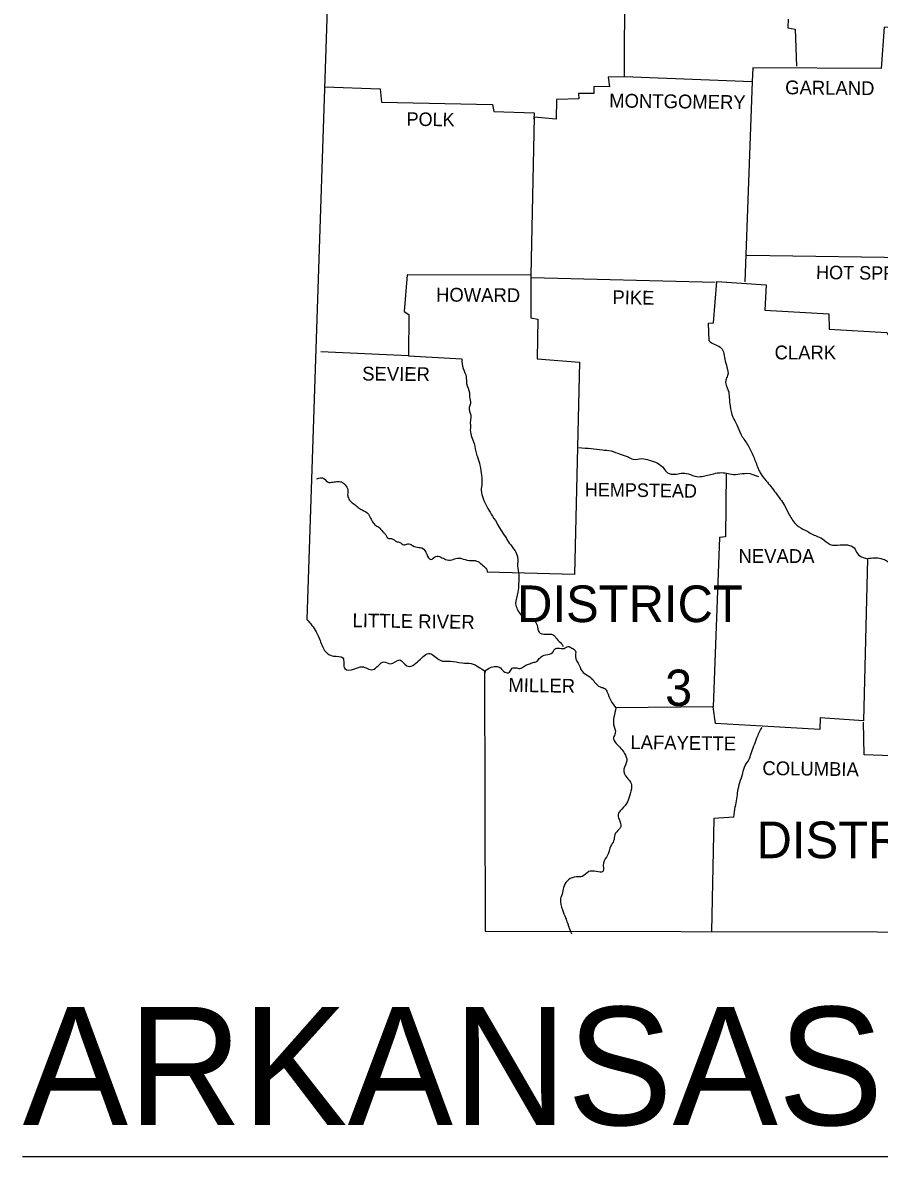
# Model space of a CAD drawing. Extents: x -42408 to 34530, y -43140 to 20491.
# Drawn here: x 1234 to 2569, y -23266 to -21499 of the extents above; entities that cross this region are included whole.
import ezdxf

# ---------------------------------------------------------------- set-up
doc = ezdxf.new("R2010")
doc.units = 0
for name, color, linetype in [('1', 7, 'Continuous'), ('2', 7, 'Continuous'), ('3', 7, 'Continuous')]:
    doc.layers.add(name, color=color, linetype=linetype)

msp = doc.modelspace()

# ---------------------------------------------------------------- linework, layer by layer
at = {"layer": '1'}
for points in [[(1618, -20239.1), (1721.6, -21071.2), (1676.6, -22429.5)], [(2172.2, -21291), (2171.2, -21583.9), (2146.2, -21584.4), (2148.2, -21599.4), (2124.1, -21598.9), (2123.6, -21609.9), (2100.1, -21609.9), (2100.6, -21617.9), (2065.6, -21618.9), (2065.1, -21649.5), (2031, -21646.5), (2025.5, -21892.8), (1832.8, -21892.3), (1828.3, -21949.4), (1835.3, -21954.4), (1834.8, -22018.5), (1698.1, -22012.5)], [(2426.6, -21493.8), (2426.1, -21507.3), (2437.6, -21509.3), (2439.6, -21567.4)], [(2740, -21511.3), (2576.3, -21506.3), (2571.7, -21570.9), (2371.5, -21569.9), (2370.5, -21591.4)], [(2370.5, -21591.4), (2171.2, -21583.9)], [(1704.1, -21599.4), (1790.7, -21602.4), (1792.7, -21623.4), (1965.9, -21626.9), (1967.9, -21638), (2031, -21640), (2030.5, -21649.5)], [(2370.5, -21591.4), (2359, -21903.3)], [(2362.5, -21861.8), (2648.8, -21865.8), (2654.4, -21818.2), (2676.9, -21818.2), (2677.4, -21778.1), (2785.5, -21779.7), (2784.5, -21803.7), (2812.6, -21805.7), (2812.6, -21849.7), (2830.6, -21851.2)], [(2025.5, -21892.8), (2025.5, -21959.4), (2036.5, -21961.4), (2035.5, -22023.5), (2101.6, -22028.5), (2093.6, -22359.4), (1957.4, -22355.9)], [(2026.5, -21896.3), (2312.9, -21903.8)], [(2303.4, -21995.4), (2302.4, -21967.9), (2310.4, -21967.4), (2315.4, -21902.8), (2392.5, -21907.8), (2390.5, -21947.4), (2490.1, -21952.9), (2490.6, -21976.9), (2580.8, -21982.4), (2596.3, -22009.5), (2586.8, -22021.5), (2591.3, -22040), (2917.7, -22052)], [(1834.8, -22018.5), (1917.9, -22023.5)], [(2329.9, -22201.2), (2328.9, -22300.8), (2319.9, -22301.8), (2309.9, -22565.7)], [(2550.7, -22334.9), (2544.2, -22587.2), (2476.6, -22582.7), (2476.1, -22601.2), (2386, -22595.7)], [(1953.4, -22510.1), (1954.4, -22915.2), (3789.4, -22918.2)], [(2386, -22595.7), (2313.4, -22591.7), (2309.9, -22565.7), (2158.2, -22567.2)], [(2759, -22648.3), (2545.2, -22640.3), (2544.2, -22589.7)], [(2341.9, -22737.4), (2310.9, -22739.4), (2307.4, -22915.7)]]:
    msp.add_lwpolyline(points, dxfattribs=at)
for points in [[(2303.4, -21995.4), (2311.4, -22000.4), (2320.9, -22005), (2325.9, -22012.5), (2327.9, -22024), (2331.4, -22036.5), (2332.4, -22049.5), (2329.4, -22056.5), (2333.4, -22072.5), (2334.9, -22083.6), (2336.4, -22096.6), (2340.4, -22114.1), (2346.9, -22126.1), (2353, -22140.6), (2363, -22156.2), (2371.5, -22173.2), (2375.5, -22182.2), (2383, -22200.7), (2392.5, -22213.2), (2407.5, -22232.3), (2421, -22251.8), (2428.6, -22266.3), (2440.1, -22282.3), (2453.1, -22290.3), (2469.6, -22298.8), (2480.1, -22303.9), (2492.1, -22312.4), (2507.7, -22313.4), (2519.2, -22313.4), (2529.7, -22317.9), (2534.7, -22326.9), (2543.7, -22332.9), (2550.7, -22334.9)], [(1917.9, -22023.5), (1920.4, -22038.5), (1924.9, -22051.5), (1925.4, -22061.5), (1929.9, -22076.5), (1929.9, -22082.1), (1931.4, -22093.1), (1929.4, -22099.1), (1931.9, -22111.1), (1931.4, -22120.1), (1931.4, -22127.6), (1931.9, -22140.1), (1935.9, -22151.1), (1939.9, -22167.7), (1942.4, -22176.2), (1946.4, -22189.2), (1948.9, -22205.2), (1949.4, -22217.2), (1948.4, -22228.2), (1951.4, -22240.8), (1956.9, -22253.3), (1963.9, -22265.3), (1972.4, -22278.8), (1978.5, -22289.3), (1986, -22300.8), (1992, -22310.4), (2001, -22322.4), (2005, -22332.4), (2005, -22346.4), (2007, -22359.4), (2006.5, -22373.9), (2005.5, -22387), (2002, -22405), (2004.5, -22413.5), (2014, -22426), (2020, -22429.5), (2030.5, -22431.5), (2035.5, -22438.5), (2038.5, -22449), (2049, -22452.5), (2060.6, -22453.5), (2066.1, -22459.6), (2073.6, -22467.6), (2076.1, -22471.6)], [(2100.6, -22161.7), (2119.6, -22163.2), (2137.2, -22165.2), (2150.7, -22166.7), (2164.7, -22171.7), (2177.2, -22176.2), (2185.2, -22179.7), (2198.7, -22178.7), (2210.3, -22181.2), (2223.3, -22185.7), (2232.8, -22194.2), (2238.8, -22200.7), (2250.3, -22203.2), (2259.8, -22201.7), (2271.3, -22202.7), (2284.4, -22206.7), (2294.9, -22206.2), (2303.4, -22204.2), (2313.4, -22201.7), (2325.9, -22200.7), (2335.4, -22202.7), (2347.9, -22203.2), (2362.5, -22201.7), (2380.5, -22206.7)], [(1692.1, -22210.2), (1703.1, -22209.7), (1710.6, -22216.2), (1715.1, -22215.7), (1723.1, -22214.7), (1730.6, -22215.2), (1736.1, -22219.7), (1740.6, -22227.7), (1740.1, -22235.3), (1740.6, -22238.3), (1744.1, -22244.8), (1750.1, -22249.8), (1756.7, -22254.8), (1762.7, -22258.8), (1772.7, -22265.3), (1773.7, -22267.3), (1777.7, -22275.3), (1782.7, -22281.8), (1788.7, -22285.8), (1795.2, -22292.8), (1798.2, -22295.8), (1803.2, -22302.8), (1808.7, -22303.3), (1816.2, -22307.9), (1821.7, -22309.4), (1827.8, -22313.4), (1833.8, -22311.4), (1841.3, -22314.4), (1851.3, -22317.4), (1856.8, -22318.4), (1863.3, -22327.9), (1869.8, -22335.9), (1877.8, -22331.4), (1892.8, -22335.9), (1902.4, -22336.4), (1910.9, -22333.9), (1917.4, -22334.4), (1929.4, -22337.4), (1936.9, -22337.4), (1944.9, -22340.4), (1952.4, -22346.4), (1957.4, -22352.9), (1957.4, -22355.9)], [(2667.4, -22308.9), (2654.4, -22317.4), (2644.3, -22321.4), (2636.8, -22323.9), (2629.8, -22325.9), (2620.8, -22331.9), (2613.8, -22336.9), (2604.3, -22341.4), (2595.3, -22344.4), (2584.3, -22340.9), (2578.3, -22337.4), (2571.7, -22334.9), (2550.7, -22334.9)], [(1676.6, -22429.5), (1691.1, -22448.5), (1697.1, -22462.1), (1705.6, -22479.6), (1718.1, -22486.6), (1732.6, -22489.1), (1735.6, -22506.1), (1750.6, -22506.6), (1762.7, -22503.1), (1779.2, -22507.6), (1796.7, -22495.6), (1806.7, -22498.6), (1821.2, -22492.6), (1832.3, -22501.6), (1851.3, -22493.6), (1868.3, -22482.6), (1884.3, -22493.1), (1899.8, -22494.6), (1918.4, -22497.1), (1932.9, -22498.1), (1945.9, -22504.6), (1955.4, -22511.1), (1953.4, -22510.1)], [(1953.4, -22510.1), (1970.9, -22502.6), (1978.5, -22505.1), (1985, -22511.6), (1992.5, -22511.6), (1996.5, -22505.6), (2004, -22505.1), (2010, -22505.6), (2016.5, -22501.6), (2022, -22499.1), (2029.5, -22496.6), (2035, -22494.6), (2040, -22489.1), (2049, -22484.6), (2059.6, -22481.1), (2062.6, -22476.1), (2067.6, -22474.1), (2077.6, -22474.6), (2084.1, -22471.6), (2089.6, -22474.1), (2094.6, -22477.6), (2095.6, -22490.6), (2099.6, -22497.6), (2105.6, -22510.1), (2114.1, -22516.6), (2122.1, -22523.1), (2125.1, -22527.1), (2133.7, -22534.7), (2141.2, -22537.2), (2144.7, -22542.7), (2150.2, -22555.7), (2158.2, -22567.2)], [(2158.2, -22567.2), (2155.2, -22581.7), (2154.7, -22593.2), (2157.2, -22606.8), (2154.7, -22613.3), (2158.7, -22622.8), (2166.2, -22630.3), (2171.7, -22638.3), (2175.2, -22649.8), (2170.7, -22662.8), (2175.7, -22676.3), (2180.2, -22681.4), (2182.7, -22689.4), (2179.2, -22704.9), (2174.7, -22716.4), (2164.7, -22727.9), (2161.7, -22733.4), (2163.2, -22740.9), (2165.7, -22752.9), (2163.2, -22756.5), (2156.7, -22765), (2154.7, -22774.5), (2150.2, -22782.5), (2145.2, -22797), (2138.7, -22809), (2137.7, -22822.5), (2127.7, -22822.5), (2116.1, -22822.5), (2105.6, -22830.1), (2096.1, -22830.6), (2084.6, -22835.1), (2077.6, -22844.6), (2075.1, -22855.1), (2072.1, -22865.1), (2075.1, -22882.1), (2079.6, -22894.1), (2083.1, -22903.7), (2089.1, -22919.2)], [(2341.9, -22737.4), (2344.4, -22721.4), (2346.9, -22708.9), (2348.4, -22696.9), (2351.5, -22683.4), (2356, -22668.8), (2360, -22656.8), (2365.5, -22648.3), (2369, -22638.3), (2373.5, -22626.3), (2378, -22613.8), (2386, -22597.7)]]:
    msp.add_spline(points, degree=3, dxfattribs=at)
at = {"layer": '2'}
msp.add_line((1233.5, -23266.2), (4582.8, -23266.2), dxfattribs=at)

# ---------------------------------------------------------------- texts
for s, height, rotation, p in [('GARLAND', 21.53, 359.3658, (2422, -21610.9)), ('MONTGOMERY', 21.53, 359.2944, (2147.7, -21631.5)), ('POLK', 21.02, 359.2152, (1831.8, -21660)), ('HOT SPRING', 21.03, 359.2216, (2470.1, -21898.8)), ('HOWARD', 21.53, 359.5145, (1877.8, -21933.9)), ('PIKE', 21.52, 359.0452, (2152.7, -21937.9)), ('SEVIER', 21.53, 359.4271, (1762.7, -22057)), ('HEMPSTEAD', 21.02, 359.1885, (2109.6, -22237.3)), ('LITTLE RIVER', 21.53, 359.1697, (1747.6, -22441.5)), ('MILLER', 21.52, 359.1319, (1990.5, -22542.2)), ('LAFAYETTE', 21.52, 359.1839, (2180.7, -22631.3)), ('COLUMBIA', 21.52, 359.2125, (2386.5, -22671.8))]:
    msp.add_text(s, height=height, rotation=rotation, dxfattribs=at).set_placement(p)
for s, height, p in [('CLARK', 21.53, (2405.6, -22024.1)), ('NEVADA', 21.53, (2349.4, -22341.4)), ('ARKANSAS HIGHWAY DISTRICT 2', 184.218, (1233.5, -23217.5))]:
    msp.add_text(s, height=height, dxfattribs=at).set_placement(p)
at = {"layer": '3'}
for s, height, p in [('DISTRICT', 57.08, (2004.2, -22433.6)), ('3', 56.6, (2235, -22564.2)), ('DISTRICT 7', 57.08, (2377.5, -22801.5))]:
    msp.add_text(s, height=height, dxfattribs=at).set_placement(p)

doc.saveas('drawing.dxf')
